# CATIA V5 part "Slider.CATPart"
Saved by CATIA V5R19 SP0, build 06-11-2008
Part number: Slider
Bounding box of the stored display mesh (mm): x -10 to 10, y -69.282 to 69.282, z -70 to 10
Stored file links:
  D:\Shriniwas\v5_r19\c16_CAT_v5r19\c16_Part\Slide curve Joint\Tut_5\Slider.CATPart
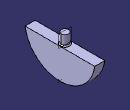
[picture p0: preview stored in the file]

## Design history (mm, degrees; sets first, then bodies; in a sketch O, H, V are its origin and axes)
Body1 (main body)
  Sketch1 on yz-plane, origin (0, 0, 0), H (0, 1, 0), V (0, 0, 1)
    arc A1 centre (0, 0) radius 70 from (-69.282, -10) to (69.282, -10) ccw
    point P1 (0, 0)
    point P2 (-69.282, -10)
    point P3 (69.282, -10)
    point P4 (0, 0)
    point P5 (-69.282, -10)
    line L1 (-69.282, -10) -> (69.282, -10)
    point P6 (69.282, -10)
    point P7 (-69.282, -10)
    reference intersected line E1 through (0, 0) direction (-1, 0) from xy-plane
    reference intersected line E3 through (0, 0) direction (0, 1) from zx-plane
    radius A1 = 70
    distance L1 P1 = 10
    coincidence: P1 V, P4 V, P6 P3, P7 A1, P2 P7, E3 P1, P2 L1, P3 L1, H P4, P2 P5, P1 H
    horizontal: L1 H, E1 H
    vertical: E3 V
    perpendicularity: E3 L1
  Pad1: profile Sketch1, direction (1, 0, 0), length 10, mirrored extent
  Point1: type OnCurve, Support edge [face of Pad1 from Sketch1.A1 | end face of Pad1], Ratio 0.5
  Sketch2 on face of Pad1 from Sketch1.L1, origin (0, 0, -10), H (1, 0, 0), V (0, 1, 0)
    circle A1 centre (0, 0) radius 7.5
    point P1 (0, 0)
    reference projected line E1 (10, 69.282) -> (10, -69.282) from edge [face of Pad1 from Sketch1.L1 | end face of Pad1]
    radius A1 = 7.5
    distance P1 E1 = 10
    coincidence: P1 H
  Pad2: profile Sketch2, direction (0, 0, 1), length 20
  Fillet1: radius 2, on edge [face of Pad1 from Sketch1.L1 | face of Pad2 from Sketch2.A1]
